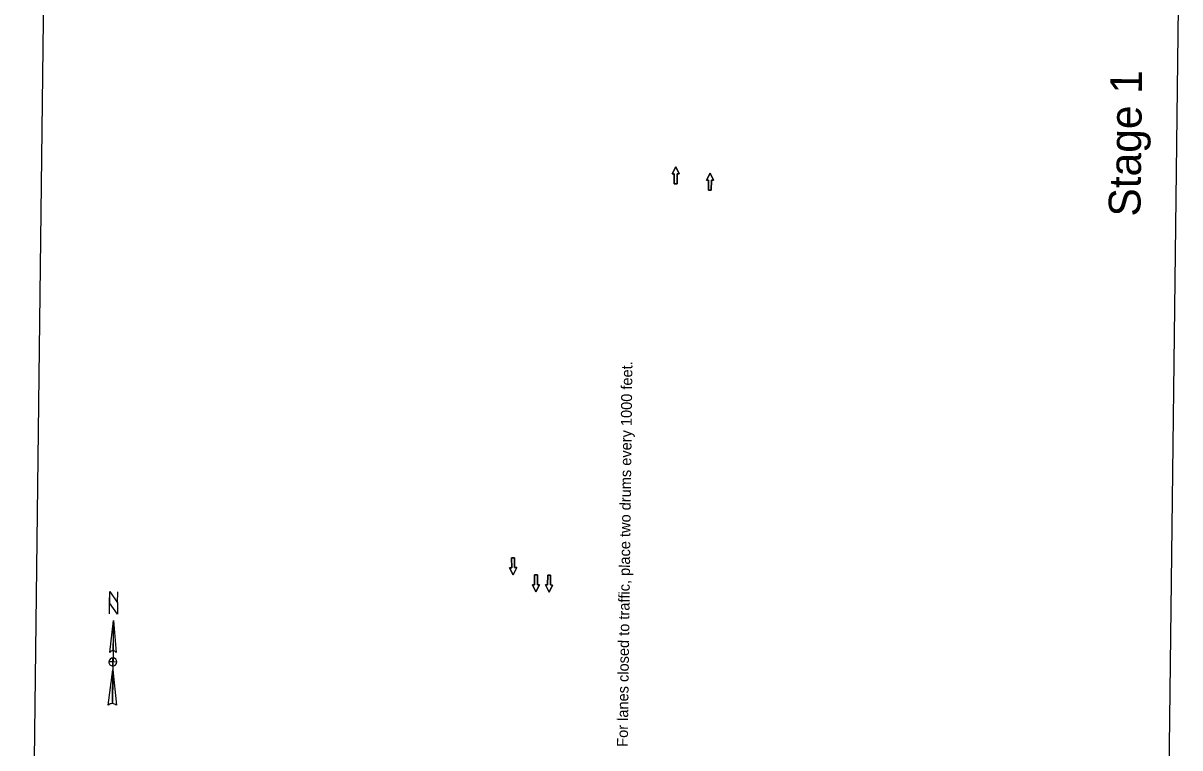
# Model space of a CAD drawing. Extents: x 4959127 to 4960275, y 3872379 to 3884458.
# Drawn here: x 4959145 to 4960164, y 3874697 to 3875336 of the extents above; entities that cross this region are included whole.
import ezdxf

# ---------------------------------------------------------------- set-up
doc = ezdxf.new("R2010")
doc.units = 0
for name, color, linetype in [('Cell', 7, 'Continuous'), ('Level 2', 7, 'Continuous'), ('Level 5', 7, 'Continuous'), ('NamedBoundary', 7, 'Continuous'), ('SheetText', 7, 'Continuous'), ('Text', 7, 'Continuous')]:
    doc.layers.add(name, color=color, linetype=linetype)

msp = doc.modelspace()

# ---------------------------------------------------------------- linework, layer by layer
at = {"layer": 'Cell'}
for p, q in [((4959224.8, 3874809.5), (4959223.9, 3874736.2)), ((4959224.8, 3874809.5), (4959227.2, 3874781.3)), ((4959221.6, 3874781.3), (4959221.6, 3874781.3)), ((4959221.7, 3874781.6), (4959222.3, 3874782.2)), ((4959220.3, 3874734.9), (4959224.2, 3874765.8)), ((4959224.3, 3874769.3), (4959224.3, 3874769.3))]:
    msp.add_line(p, q, dxfattribs=at)
for points in [[(4959221.3, 3874815.2), (4959221.6, 3874834.9), (4959228.5, 3874824.9), (4959228.6, 3874834.8)], [(4959221.6, 3874781.3), (4959224.8, 3874809.5), (4959224.4, 3874782.7)], [(4959224.3, 3874769.3), (4959224.3, 3874772.9), (4959220.8, 3874772.9)], [(4959227.8, 3874772.8), (4959224.3, 3874772.9), (4959224.4, 3874776.4)], [(4959223.9, 3874736.2), (4959224.2, 3874765.8), (4959227.4, 3874734.8)]]:
    msp.add_lwpolyline(points, dxfattribs=at)
msp.add_lwpolyline([(4959228.4, 3874815.1), (4959221.4, 3874825), (4959221.6, 3874834.9), (4959228.5, 3874824.9)], close=True, dxfattribs=at)
for centre, radius, start, end in [((4959224.4, 3874779.2), 3.52, 89.3179, 142.4233), ((4959224.4, 3874779.2), 3.52, 36.1456, 89.3194), ((4959224.3, 3874772.9), 3.52, 89.2975, 179.2975), ((4959224.3, 3874772.9), 3.52, 179.2975, 269.2975), ((4959224.3, 3874772.9), 3.52, 269.2975, 359.2975), ((4959224.3, 3874772.9), 3.52, 359.2975, 89.2975), ((4959223.8, 3874731.1), 5.1, 89.2869, 132.9165), ((4959223.8, 3874731.1), 5.11, 45.6996, 89.2982)]:
    msp.add_arc(centre, radius, start, end, dxfattribs=at)
at = {"layer": 'Level 2'}
for points in [[(4959721.4, 3875194), (4959718.9, 3875194.1), (4959719, 3875202.8), (4959717.1, 3875202.8), (4959720.3, 3875209.1), (4959723.4, 3875202.8), (4959721.5, 3875202.8)], [(4959751.6, 3875188.5), (4959749.1, 3875188.6), (4959749.2, 3875197.3), (4959747.3, 3875197.3), (4959750.5, 3875203.6), (4959753.6, 3875197.3), (4959751.7, 3875197.3)], [(4959575.6, 3874864.7), (4959578.1, 3874864.7), (4959578.3, 3874856), (4959580.1, 3874856), (4959577.1, 3874849.7), (4959573.9, 3874855.9), (4959575.8, 3874855.9)], [(4959595.9, 3874849.6), (4959598.4, 3874849.6), (4959598.3, 3874840.8), (4959600.2, 3874840.8), (4959597, 3874834.6), (4959593.9, 3874840.9), (4959595.8, 3874840.8)], [(4959607.5, 3874849.4), (4959610, 3874849.4), (4959609.9, 3874840.7), (4959611.8, 3874840.6), (4959608.6, 3874834.4), (4959605.5, 3874840.7), (4959607.4, 3874840.7)]]:
    msp.add_lwpolyline(points, close=True, dxfattribs=at)
at = {"layer": 'Level 5'}
for points in [[(4959721.5, 3875202.8), (4959723.4, 3875202.8), (4959720.3, 3875209.1), (4959717.1, 3875202.8), (4959719, 3875202.8), (4959718.9, 3875194.1), (4959721.4, 3875194), (4959721.5, 3875202.8)], [(4959751.7, 3875197.3), (4959753.6, 3875197.3), (4959750.5, 3875203.6), (4959747.3, 3875197.3), (4959749.2, 3875197.3), (4959749.1, 3875188.6), (4959751.6, 3875188.5), (4959751.7, 3875197.3)], [(4959575.8, 3874855.9), (4959573.9, 3874855.9), (4959577.1, 3874849.7), (4959580.1, 3874856), (4959578.3, 3874856), (4959578.1, 3874864.7), (4959575.6, 3874864.7), (4959575.8, 3874855.9)], [(4959595.8, 3874840.8), (4959593.9, 3874840.9), (4959597, 3874834.6), (4959600.2, 3874840.8), (4959598.3, 3874840.8), (4959598.4, 3874849.6), (4959595.9, 3874849.6), (4959595.8, 3874840.8)], [(4959607.4, 3874840.7), (4959605.5, 3874840.7), (4959608.6, 3874834.4), (4959611.8, 3874840.6), (4959609.9, 3874840.7), (4959610, 3874849.4), (4959607.5, 3874849.4), (4959607.4, 3874840.7)]]:
    msp.add_lwpolyline(points, dxfattribs=at)
at = {"layer": 'NamedBoundary'}
msp.add_lwpolyline([(4959145.3, 3873891.3), (4960145.2, 3873879.1), (4960164.4, 3875446.5), (4959164.5, 3875458.7)], close=True, dxfattribs=at)

# ---------------------------------------------------------------- texts
at = {"layer": 'SheetText'}
msp.add_text('For lanes closed to traffic, place two drums every 1000 feet.', height=9.6, rotation=89.3042, dxfattribs=at).set_placement((4959678, 3874698.1))
at = {"layer": 'Text'}
msp.add_text('Stage 1', height=28, rotation=89.2975, dxfattribs=at).set_placement((4960129.6, 3875165.1))

doc.saveas('drawing.dxf')
